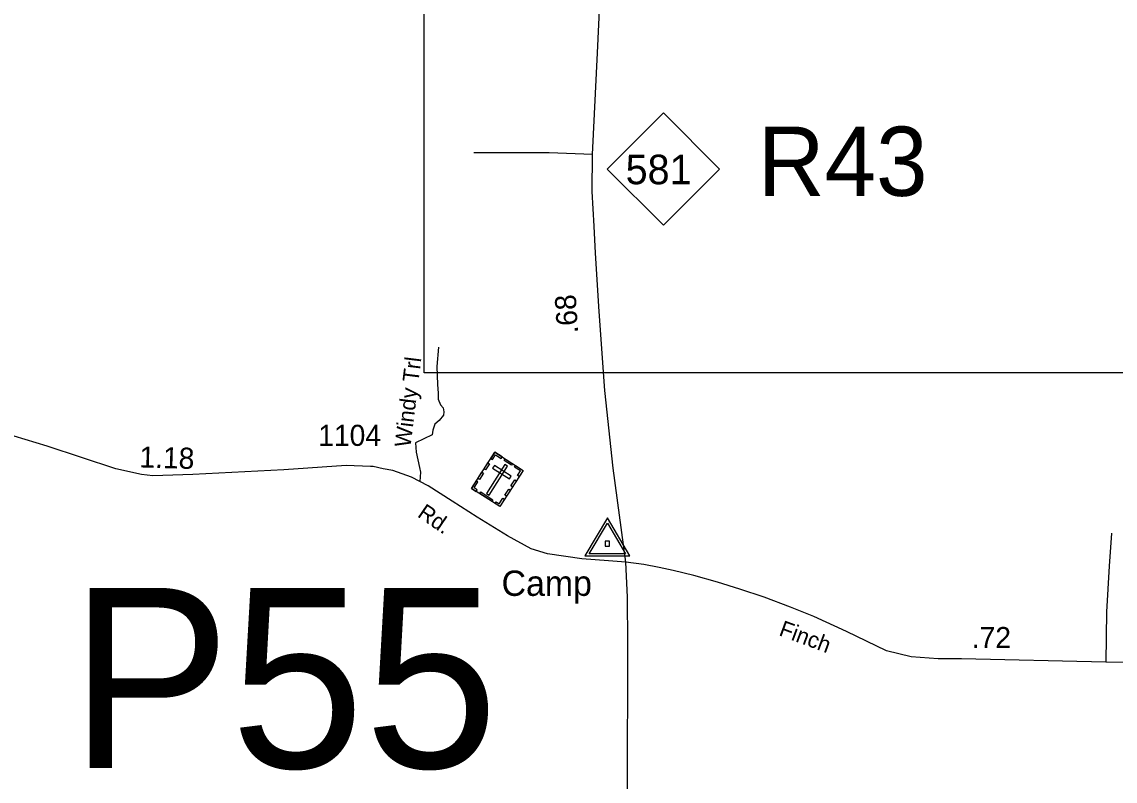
# Model space of a CAD drawing. Extents: x 2220236 to 2384410, y 720751 to 894131.
# Drawn here: x 2257585 to 2264060, y 733739 to 738237 of the extents above; entities that cross this region are included whole.
import ezdxf

# ---------------------------------------------------------------- set-up
doc = ezdxf.new("R2010")
doc.units = 0
doc.layers.add('Default', color=7, linetype='Continuous')

msp = doc.modelspace()

# ---------------------------------------------------------------- linework, layer by layer
at = {"layer": 'Default'}
for points in [[(2259967.8, 744228.7), (2273241.2, 744228.7), (2273241.2, 736157.5), (2259967.8, 736157.5), (2259967.8, 744228.7)], [(2261161.5, 735036.6), (2261087, 735593.5), (2261037.3, 736052.5), (2261004.4, 736520.3), (2260982.5, 736866.7), (2260975.2, 737026), (2260962.1, 737232.1), (2260965.7, 737451.4), (2260993.5, 738053.7), (2261072.2, 739690.5)], [(2260965.7, 737451.4), (2260708.6, 737461.6), (2260262.3, 737461.6)], [(2260052, 736309.6), (2260043, 736195.6), (2260046, 736087.6), (2260050.6, 736037.7), (2260050.8, 736001.7), (2260065.1, 735967.8), (2260079.4, 735949.9), (2260083.5, 735926), (2260081.6, 735906.1), (2260056, 735875.8), (2260030.2, 735853.6), (2260018.6, 735817.4), (2260014.9, 735789.5), (2259916.9, 735742.6), (2259920.5, 735688.5), (2259939.5, 735596.4), (2259945.3, 735568.6), (2259941, 735514.6)], [(2261161.5, 735036.6), (2261059.2, 735043.9), (2260901.5, 735055.6), (2260698.4, 735086.3), (2260602, 735115.5), (2260460.3, 735191.5), (2260281.3, 735302.6), (2260133.8, 735397.6), (2259992.1, 735488.2), (2259941, 735514.6), (2259892, 735539.4), (2259838, 735559.9), (2259782.5, 735578.9), (2259724, 735589.1), (2259665.6, 735602.3), (2259649.5, 735603.7), (2259506.4, 735609.6), (2259136.8, 735583.3), (2258597.7, 735555.5), (2258361.1, 735548.2), (2258292.4, 735555.5), (2258140.5, 735589.1), (2257734.4, 735723.6), (2257538.6, 735782.1)], [(2264038.6, 735207.6), (2264025.5, 735013.2), (2264010.1, 734741.3), (2264005, 734444.5)], [(2264885.9, 734421.2), (2264604, 734427), (2264372.4, 734437.2), (2264005, 734444.5), (2263149.7, 734463.5), (2263012.4, 734463.5), (2262851.7, 734475.2), (2262706.3, 734511.8), (2262469.7, 734625.8), (2262276.1, 734715), (2262137.3, 734770.5), (2261982.5, 734829), (2261837.9, 734877.2), (2261704.9, 734918.2), (2261564.7, 734957.6), (2261441.7, 734987.2), (2261360.2, 735004.4), (2261268.1, 735021.9), (2261161.5, 735036.6)], [(2261902.9, 731673.5), (2261686.6, 731967.9), (2261616.5, 732097.1), (2261574.7, 732193.6), (2261434.6, 732583.2), (2261374.5, 732754.3), (2261274.5, 733038.3), (2261232.6, 733176.6), (2261209, 733265.8), (2261194.4, 733331.4), (2261176.2, 733477), (2261172.6, 733660.9), (2261173.9, 734557.1), (2261172.4, 734829), (2261161.5, 735036.6)]]:
    msp.add_lwpolyline(points, dxfattribs=at)
for points in [[(2261051.9, 737364.4), (2261384.9, 737697.4), (2261717.9, 737364.4), (2261384.9, 737031.4)], [(2260385.8, 735687.6), (2260553.2, 735580), (2260415.5, 735365.8), (2260248.1, 735473.5)], [(2260362.3, 735651.2), (2260371.9, 735645.1), (2260389.3, 735672.2), (2260423.4, 735650.2), (2260429.4, 735659.6), (2260385.8, 735687.6)], [(2260448.1, 735647.6), (2260491.7, 735619.6), (2260485.5, 735610), (2260441.9, 735638)], [(2260322.2, 735588.8), (2260345.7, 735625.3), (2260355.2, 735619.1), (2260331.8, 735582.7)], [(2260461.6, 735604), (2260445.9, 735614.1), (2260336.3, 735443.6), (2260352, 735433.5)], [(2260383.3, 735608.3), (2260373.2, 735592.6), (2260472.2, 735529), (2260482.3, 735544.7)], [(2260529.9, 735543.5), (2260520.3, 735549.6), (2260537.7, 735576.7), (2260503.6, 735598.6), (2260509.6, 735608), (2260553.3, 735579.9)], [(2260275.9, 735455.6), (2260282.1, 735465.3), (2260263.6, 735477.2), (2260285.5, 735511.2), (2260276.1, 735517.2), (2260248.1, 735473.5)], [(2260285.9, 735532.3), (2260309.3, 735568.7), (2260318.9, 735562.6), (2260295.4, 735526.2)], [(2260480.7, 735488.2), (2260504.2, 735524.6), (2260513.7, 735518.5), (2260490.3, 735482)], [(2260302.6, 735452), (2260374, 735406.2), (2260367.8, 735396.6), (2260296.5, 735442.5)], [(2260445.1, 735432.7), (2260468.5, 735469.2), (2260478.1, 735463), (2260454.6, 735426.6)], [(2260387.7, 735383.7), (2260393.9, 735393.4), (2260412.4, 735381.5), (2260434.2, 735415.5), (2260443.6, 735409.5), (2260415.5, 735365.8)], [(2261186.6, 735073.1), (2261052.6, 735299.2), (2260919.2, 735073.1)], [(2261160.7, 735085.2), (2260945.1, 735085.2), (2261052.6, 735267.4)], [(2261064.9, 735131.8), (2261064.9, 735160.1), (2261040.7, 735160.1), (2261040.7, 735131.8)]]:
    msp.add_lwpolyline(points, close=True, dxfattribs=at)

# ---------------------------------------------------------------- texts
for s, height, p in [('R43', 410.1, (2261943.4, 737205.8)), ('581', 175, (2261161, 737274.7)), ('1104', 125, (2259340.2, 735724.9)), ('Camp', 150, (2260426.1, 734836.5)), ('P55', 1066.27, (2257869, 733817.6))]:
    msp.add_text(s, height=height, dxfattribs=at).set_placement(p)
for s, height, rotation, p in [('.68', 125, 93.61921, (2260879.8, 736393.5)), ('Windy Trl', 95, 83.02709, (2259886.2, 735713.1)), ('1.18', 125, 358.30566, (2258279.6, 735597.6)), ('Rd.', 95, 325.74199, (2259922.3, 735309)), ('Finch', 95, 339.70486, (2262063.6, 734604.1)), ('.72', 125, 359.84518, (2263211, 734527.7))]:
    msp.add_text(s, height=height, rotation=rotation, dxfattribs=at).set_placement(p)

doc.saveas('drawing.dxf')
